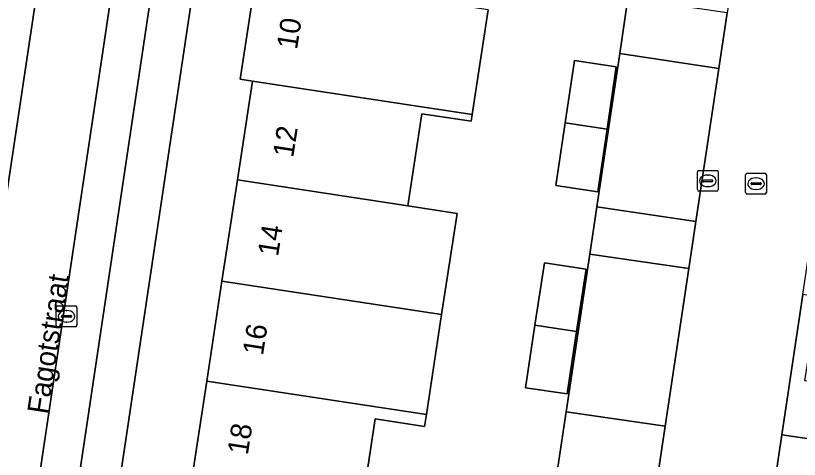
# Model space of a CAD drawing. Extents: x 164148 to 165261, y 382513 to 383432.
# Drawn here: x 164310.2 to 164347.95, y 382801.38 to 382822.75 of the extents above; entities that cross this region are included whole.
import ezdxf

# ---------------------------------------------------------------- set-up
doc = ezdxf.new("R2010")
doc.units = 0
for name, color, linetype in [('IMGEO_Erf', 7, 'Continuous'), ('IMGEO_Kolk', 7, 'Continuous'), ('IMGEO_Openbare_ruimte_label', 7, 'Continuous'), ('IMGEO_Pand', 7, 'Continuous'), ('IMGEO_Pand_nummerreeks', 7, 'Continuous'), ('IMGEO_Parkeervlak_open', 7, 'Continuous'), ('IMGEO_Rijbaan_lokaal_open', 7, 'Continuous'), ('IMGEO_Rioolput', 7, 'Continuous'), ('IMGEO_Voetpad_open', 7, 'Continuous')]:
    doc.layers.add(name, color=color, linetype=linetype)

msp = doc.modelspace()

# ---------------------------------------------------------------- linework, layer by layer
at = {"layer": 'IMGEO_Erf'}
for points in [[(164336.319, 382801.003), (164336.717, 382803.665), (164337.854, 382811.264), (164338.195, 382813.542), (164339.299, 382820.92), (164339.698, 382823.586), (164340.106, 382826.312), (164340.321, 382827.745), (164340.709, 382830.337), (164341.126, 382833.13), (164342.26, 382840.703), (164342.463, 382842.062), (164321.904, 382845.071), (164308.618, 382756.371)], [(164318.667, 382800.332), (164319.402, 382805.15), (164320.137, 382809.967), (164320.88, 382814.834), (164321.607, 382819.602), (164321.014, 382819.693), (164321.797, 382824.824)], [(164332.963, 382823.024), (164332.195, 382817.987), (164332.145, 382817.661), (164329.765, 382818.024), (164329.088, 382813.584), (164331.465, 382813.222), (164330.722, 382808.352), (164329.987, 382803.535), (164329.9, 382802.965), (164327.52, 382803.328), (164326.872, 382799.08)]]:
    msp.add_lwpolyline(points, dxfattribs=at)
for points in [[(164339.134, 382820.279), (164338.69, 382817.28), (164338.243, 382814.262), (164336.223, 382814.569), (164336.672, 382817.581), (164337.12, 382820.593)], [(164337.682, 382810.545), (164337.223, 382807.531), (164336.765, 382804.525), (164334.757, 382804.823), (164335.218, 382807.837), (164335.678, 382810.851)]]:
    msp.add_lwpolyline(points, close=True, dxfattribs=at)
at = {"layer": 'IMGEO_Kolk'}
for p, q in [((164343.044, 382814.368), (164343.044, 382815.22)), ((164343.119, 382815.294), (164343.971, 382815.294)), ((164344.045, 382815.22), (164344.045, 382814.368)), ((164343.303, 382814.788), (164343.303, 382814.8)), ((164343.346, 382814.837), (164343.744, 382814.837)), ((164343.532, 382815.074), (164343.557, 382815.074)), ((164343.787, 382814.8), (164343.787, 382814.788)), ((164343.741, 382814.751), (164343.343, 382814.751)), ((164343.555, 382814.514), (164343.53, 382814.514)), ((164343.971, 382814.294), (164343.119, 382814.294)), ((164312.225, 382808.767), (164313.077, 382808.767)), ((164312.15, 382807.841), (164312.15, 382808.693)), ((164312.638, 382808.547), (164312.663, 382808.547)), ((164313.151, 382808.693), (164313.151, 382807.841)), ((164312.409, 382808.261), (164312.409, 382808.273)), ((164312.847, 382808.224), (164312.449, 382808.224)), ((164312.452, 382808.31), (164312.85, 382808.31)), ((164312.893, 382808.273), (164312.893, 382808.261)), ((164313.077, 382807.767), (164312.225, 382807.767)), ((164312.661, 382807.987), (164312.636, 382807.987))]:
    msp.add_line(p, q, dxfattribs=at)
for points in [[(164343.044, 382814.368), (164343.044, 382815.22)], [(164343.119, 382815.294), (164343.971, 382815.294)], [(164344.045, 382815.22), (164344.045, 382814.368)], [(164343.971, 382814.294), (164343.119, 382814.294)], [(164312.225, 382808.767), (164313.077, 382808.767)], [(164312.15, 382807.841), (164312.15, 382808.693)], [(164313.151, 382808.693), (164313.151, 382807.841)], [(164313.077, 382807.767), (164312.225, 382807.767)]]:
    msp.add_lwpolyline(points, dxfattribs=at)
for centre, radius, start, end in [((164343.121, 382815.218), 0.0765, 91.552, 178.448), ((164343.121, 382815.218), 0.0765, 91.552, 178.448), ((164343.969, 382815.218), 0.0765, 1.552, 88.448), ((164343.969, 382815.218), 0.0765, 1.552, 88.448), ((164343.343, 382814.797), 0.0403, 85.8775, 175.7526), ((164343.34, 382814.787), 0.0366, 178.938, 274.7102), ((164343.744, 382814.794), 0.043, 264.8664, 352.4533), ((164343.748, 382814.799), 0.0386, 1.7309, 96.639), ((164343.121, 382814.37), 0.0765, 181.552, 268.448), ((164343.121, 382814.37), 0.0765, 181.552, 268.448), ((164343.969, 382814.37), 0.0765, 271.552, 358.448), ((164343.969, 382814.37), 0.0765, 271.552, 358.448), ((164312.227, 382808.691), 0.0765, 91.552, 178.448), ((164312.227, 382808.691), 0.0765, 91.552, 178.448), ((164313.075, 382808.691), 0.0765, 1.552, 88.448), ((164313.075, 382808.691), 0.0765, 1.552, 88.448), ((164312.449, 382808.27), 0.0403, 85.8775, 175.7526), ((164312.446, 382808.26), 0.0366, 178.938, 274.7102), ((164312.85, 382808.267), 0.043, 264.8664, 352.4533), ((164312.854, 382808.272), 0.0386, 1.7309, 96.639), ((164312.227, 382807.843), 0.0765, 181.552, 268.448), ((164312.227, 382807.843), 0.0765, 181.552, 268.448), ((164313.075, 382807.843), 0.0765, 271.552, 358.448), ((164313.075, 382807.843), 0.0765, 271.552, 358.448)]:
    msp.add_arc(centre, radius, start, end, dxfattribs=at)
for centre, major_axis, ratio, start_param, end_param in [((164343.531, 382814.794), (-0.387, 0.002), 0.722429, 4.712389, 7.853982), ((164343.556, 382814.794), (-0.39, 0.002), 0.717154, 1.570796, 4.712389), ((164312.637, 382808.267), (-0.387, 0.002), 0.722429, 4.712389, 7.853982), ((164312.662, 382808.267), (-0.39, 0.002), 0.717154, 1.570796, 4.712389)]:
    msp.add_ellipse(centre, major_axis=major_axis, ratio=ratio, start_param=start_param, end_param=end_param, dxfattribs=at)
at = {"layer": 'IMGEO_Pand'}
for points in [[(164332.963, 382823.024), (164330.589, 382823.386), (164330.603, 382823.48), (164321.797, 382824.824), (164321.014, 382819.693), (164321.607, 382819.602), (164332.195, 382817.987)], [(164337.12, 382820.593), (164336.672, 382817.581), (164338.69, 382817.28), (164339.134, 382820.279)], [(164329.765, 382818.024), (164332.145, 382817.661), (164332.195, 382817.987), (164321.607, 382819.602), (164320.88, 382814.834), (164329.088, 382813.584)], [(164338.69, 382817.28), (164336.672, 382817.581), (164336.223, 382814.569), (164338.243, 382814.262)], [(164331.465, 382813.222), (164329.088, 382813.584), (164320.88, 382814.834), (164320.137, 382809.967), (164330.722, 382808.352)], [(164335.678, 382810.851), (164335.218, 382807.837), (164337.223, 382807.531), (164337.682, 382810.545)], [(164330.722, 382808.352), (164320.137, 382809.967), (164319.402, 382805.15), (164329.987, 382803.535)], [(164337.223, 382807.531), (164335.218, 382807.837), (164334.757, 382804.823), (164336.765, 382804.525)], [(164327.52, 382803.328), (164329.9, 382802.965), (164329.987, 382803.535), (164319.402, 382805.15), (164318.667, 382800.332), (164326.872, 382799.08)]]:
    msp.add_lwpolyline(points, close=True, dxfattribs=at)
at = {"layer": 'IMGEO_Parkeervlak_open'}
for points in [[(164317.721, 382843.296), (164305.588, 382762.12)], [(164307.907, 382764.872), (164319.154, 382840.039)]]:
    msp.add_lwpolyline(points, dxfattribs=at)
for points in [[(164344.073, 382820.206), (164339.299, 382820.92), (164338.195, 382813.542), (164342.967, 382812.827)], [(164342.629, 382810.568), (164337.854, 382811.264), (164336.717, 382803.665), (164341.49, 382802.969)], [(164352.274, 382804.514), (164351.421, 382804.648), (164348.214, 382805.152), (164348.44, 382806.605), (164352.49, 382805.954), (164352.883, 382808.572), (164348.119, 382809.31), (164347.108, 382802.559), (164351.878, 382801.866)]]:
    msp.add_lwpolyline(points, close=True, dxfattribs=at)
at = {"layer": 'IMGEO_Rijbaan_lokaal_open'}
for points in [[(164318.45, 382848.222), (164320.963, 382865.023), (164320.969, 382865.121), (164317.478, 382865.636), (164317.049, 382862.672), (164314.278, 382844.244), (164311.541, 382826.019), (164308.94, 382808.745), (164306.009, 382789.028), (164302.972, 382768.762), (164301.88, 382761.702), (164305.445, 382761.166), (164305.559, 382761.978), (164305.588, 382762.12), (164317.721, 382843.296)], [(164346.706, 382799.875), (164347.108, 382802.559), (164348.119, 382809.31), (164348.538, 382812.111), (164349.669, 382819.657), (164349.993, 382821.825), (164351.128, 382829.402), (164351.515, 382831.984), (164352.523, 382838.717), (164352.791, 382840.504), (164352.276, 382840.585), (164347.755, 382841.26), (164347.238, 382841.326), (164347.039, 382839.997), (164345.904, 382832.423), (164345.486, 382829.632), (164344.474, 382822.879), (164344.073, 382820.206), (164342.967, 382812.827), (164342.629, 382810.568), (164341.49, 382802.969), (164341.089, 382800.293)]]:
    msp.add_lwpolyline(points, dxfattribs=at)
at = {"layer": 'IMGEO_Rioolput'}
for p, q in [((164345.369, 382814.23), (164345.369, 382815.082)), ((164345.444, 382815.156), (164346.296, 382815.156)), ((164345.857, 382814.936), (164345.882, 382814.936)), ((164346.37, 382815.082), (164346.37, 382814.23)), ((164345.628, 382814.65), (164345.628, 382814.662)), ((164346.066, 382814.613), (164345.668, 382814.613)), ((164345.671, 382814.699), (164346.069, 382814.699)), ((164346.112, 382814.662), (164346.112, 382814.65)), ((164346.296, 382814.156), (164345.444, 382814.156)), ((164345.88, 382814.376), (164345.855, 382814.376))]:
    msp.add_line(p, q, dxfattribs=at)
for points in [[(164345.369, 382814.23), (164345.369, 382815.082)], [(164345.444, 382815.156), (164346.296, 382815.156)], [(164346.37, 382815.082), (164346.37, 382814.23)], [(164346.296, 382814.156), (164345.444, 382814.156)]]:
    msp.add_lwpolyline(points, dxfattribs=at)
for centre, radius, start, end in [((164345.446, 382815.08), 0.0765, 91.552, 178.448), ((164345.446, 382815.08), 0.0765, 91.552, 178.448), ((164346.294, 382815.08), 0.0765, 1.552, 88.448), ((164346.294, 382815.08), 0.0765, 1.552, 88.448), ((164345.668, 382814.659), 0.0403, 85.8775, 175.7526), ((164345.665, 382814.649), 0.0366, 178.938, 274.7102), ((164346.069, 382814.656), 0.043, 264.8664, 352.4533), ((164346.073, 382814.661), 0.0386, 1.7309, 96.639), ((164345.446, 382814.232), 0.0765, 181.552, 268.448), ((164345.446, 382814.232), 0.0765, 181.552, 268.448), ((164346.294, 382814.232), 0.0765, 271.552, 358.448), ((164346.294, 382814.232), 0.0765, 271.552, 358.448)]:
    msp.add_arc(centre, radius, start, end, dxfattribs=at)
for centre, major_axis, ratio, start_param, end_param in [((164345.856, 382814.656), (-0.387, 0.002), 0.722429, 4.712389, 7.853982), ((164345.881, 382814.656), (-0.39, 0.002), 0.717154, 1.570796, 4.712389)]:
    msp.add_ellipse(centre, major_axis=major_axis, ratio=ratio, start_param=start_param, end_param=end_param, dxfattribs=at)
at = {"layer": 'IMGEO_Voetpad_open'}
for points in [[(164308.94, 382808.745), (164311.541, 382826.019), (164314.278, 382844.244), (164317.049, 382862.672), (164317.478, 382865.636), (164317.658, 382866.876)], [(164306.314, 382754.511), (164308.618, 382756.371), (164321.904, 382845.071), (164322.133, 382846.618)], [(164319.154, 382840.039), (164307.907, 382764.872)]]:
    msp.add_lwpolyline(points, dxfattribs=at)
for points in [[(164344.474, 382822.879), (164339.698, 382823.586), (164339.299, 382820.92), (164344.073, 382820.206)], [(164342.967, 382812.827), (164338.195, 382813.542), (164337.854, 382811.264), (164342.629, 382810.568)], [(164341.49, 382802.969), (164336.717, 382803.665), (164336.319, 382801.003), (164341.089, 382800.293)], [(164351.878, 382801.866), (164347.108, 382802.559), (164346.706, 382799.875), (164351.47, 382799.147)]]:
    msp.add_lwpolyline(points, close=True, dxfattribs=at)

# ---------------------------------------------------------------- texts
at = {"layer": 'IMGEO_Openbare_ruimte_label'}
msp.add_text('Fagotstraat', height=1, rotation=81.2538, dxfattribs=at).set_placement((164311.736, 382803.518))
at = {"layer": 'IMGEO_Pand_nummerreeks'}
for s, rotation, p in [('10', 81.1251, (164323.752, 382821.086)), ('12', 81.1308, (164323.566, 382815.881)), ('14', 81.1194, (164322.839, 382811.121)), ('16', 81.1251, (164322.111, 382806.351)), ('18', 81.1308, (164321.38, 382801.556))]:
    msp.add_text(s, height=1, rotation=rotation, dxfattribs=at).set_placement(p)

doc.saveas('drawing.dxf')
